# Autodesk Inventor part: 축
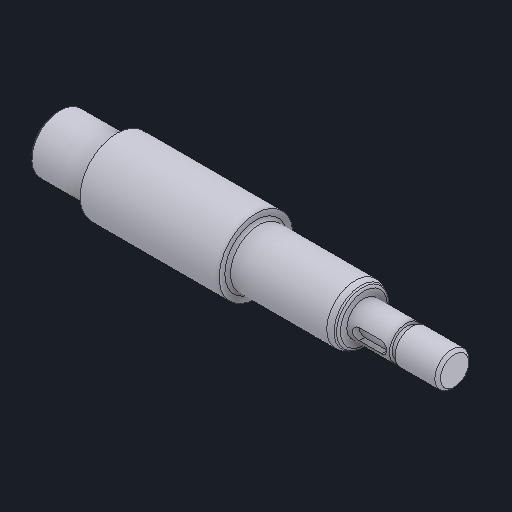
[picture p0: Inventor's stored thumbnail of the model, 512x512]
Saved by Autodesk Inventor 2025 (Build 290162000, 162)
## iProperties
Created: 2025-08
Part Number: 축
Material: 강철, 연강
Document SubType Name: Modeling
Designer: infra14
Density: 7.86 g/cm^3
Appearance: 기본값
Author: jhkim
Sending System: Autodesk Inventor 2026
Preprocessor: ST-DEVELOPER v20.1
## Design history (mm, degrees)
feature "솔리드2"
node "솔리드1"
